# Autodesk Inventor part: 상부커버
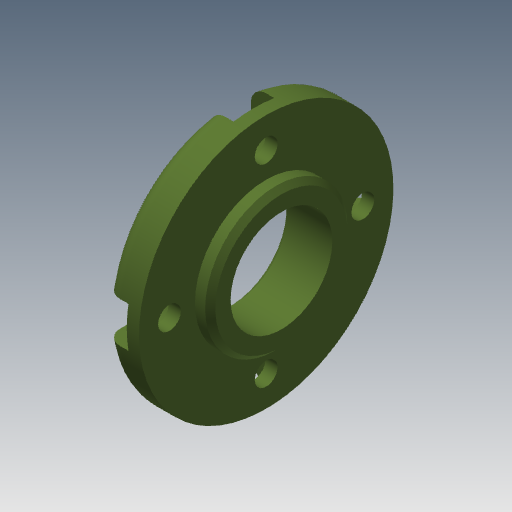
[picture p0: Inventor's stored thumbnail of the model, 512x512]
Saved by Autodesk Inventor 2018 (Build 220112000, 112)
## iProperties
Created: 2019-01
Part Number: 상부커버
Material: 알루미늄 6061
Document SubType Name: Modeling
Designer: mduedu
Density: 2.71 g/cm^3
Appearance: 올리브 녹색
Mass: 28.8858 g
Surface Area: 53.2237 cm^2
Volume: 10.659 cm^3
Author: mduedu
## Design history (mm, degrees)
sketch "스케치1"
  geometry: L1 (0, 0)-(7, 0); L2 (7, 0)-(7, 25); L3 (7, 25)-(0, 25); L4 (0, 25)-(0, 0); L5 (7, 0)-(10, 0); L6 (10, 0)-(10, 14); L7 (10, 14)-(7, 14); L8 (7, 14)-(7, 0)
  constraints: 16 end point, 4 parallel, 2 horizontal, 2 perpendicular
  dimensions: "d0" = 50 diameter of L3 L1; "d2" = 10 distance between parallel lines of L6 L4; "d3" = 7 distance of L2.end L3.end; "d4" = 28 diameter of L7 L5
revolve "회전1" sketch "스케치1" stored, may be unused: angle "d5" = 90 deg
sketch "스케치2"
  geometry: C1 r 10 at (0, 0); 1 further point
  constraints: 1 centre point, 1 coincident
  dimensions: "d6" = 20 diameter of C1
extrude "돌출1" cut sketch "스케치2" extent not by distance; stored distance "d7" = 10; taper "d8" = 0 deg
chamfer "모따기1" distance "d9" = 1; stored, may be unused: second distance "d10" = 2, angle "d11" = 45 deg
fillet "모깎기1" dims "d12" = 3
sketch "스케치3" dims "d13" = 38
  geometry: 6 further points
  constraints: 2 vertical alignment, 1 coincident, 7 other
  dimensions: "d16" = 360 deg dimension on point (0, 0) point (0, 19) (derived)
chamfer "모따기2" distance "d18" = 1; stored, may be unused: second distance "d19" = 2, angle "d20" = 45 deg
sketch "스케치4"
  geometry: 4 further points
  constraints: 4 other
hole "구멍1" sketch "스케치4" at (-19, 0), (0, -19), (19, 0), (0, 19) diameter "d21" = 4.5; stored, may be unused: countersink angle "d25" = 90 deg, drill point angle "d27" = 0 deg; dims "d22" = 6, "d23" = 8, "d24" = 4.6, "d26" = 8
sketch "스케치5"
  geometry: L1 (-4, 0)-(-4, 5.678); L2 (4, 0)-(4, 5.678); A1 r 4 centre (0, 0) between (-2.841, 2.816) and (2.841, 2.816) reference; A2 r 25 centre (0, -19) between (-4, 5.678) and (4, 5.678) reference; A3 r 4 centre (0, 0) between (-4, 0) and (4, 0); A4 r 25 centre (0, -19) between (4, 5.678) and (-4, 5.678); A5 r 4 centre (0, 0) between (4, 0) and (-4, 0); 1 further point
  constraints: 10 point on circle, 4 end point, 3 centre point, 2 coincident, 2 tangent, 1 parallel, 1 vertical
extrude "돌출2" cut sketch "스케치5" extent not by distance; stored distance "d28" = 10; taper "d29" = 0 deg
node "솔리드1"
pattern_circular "원형 패턴1" dims angle "d31" = 360 deg
